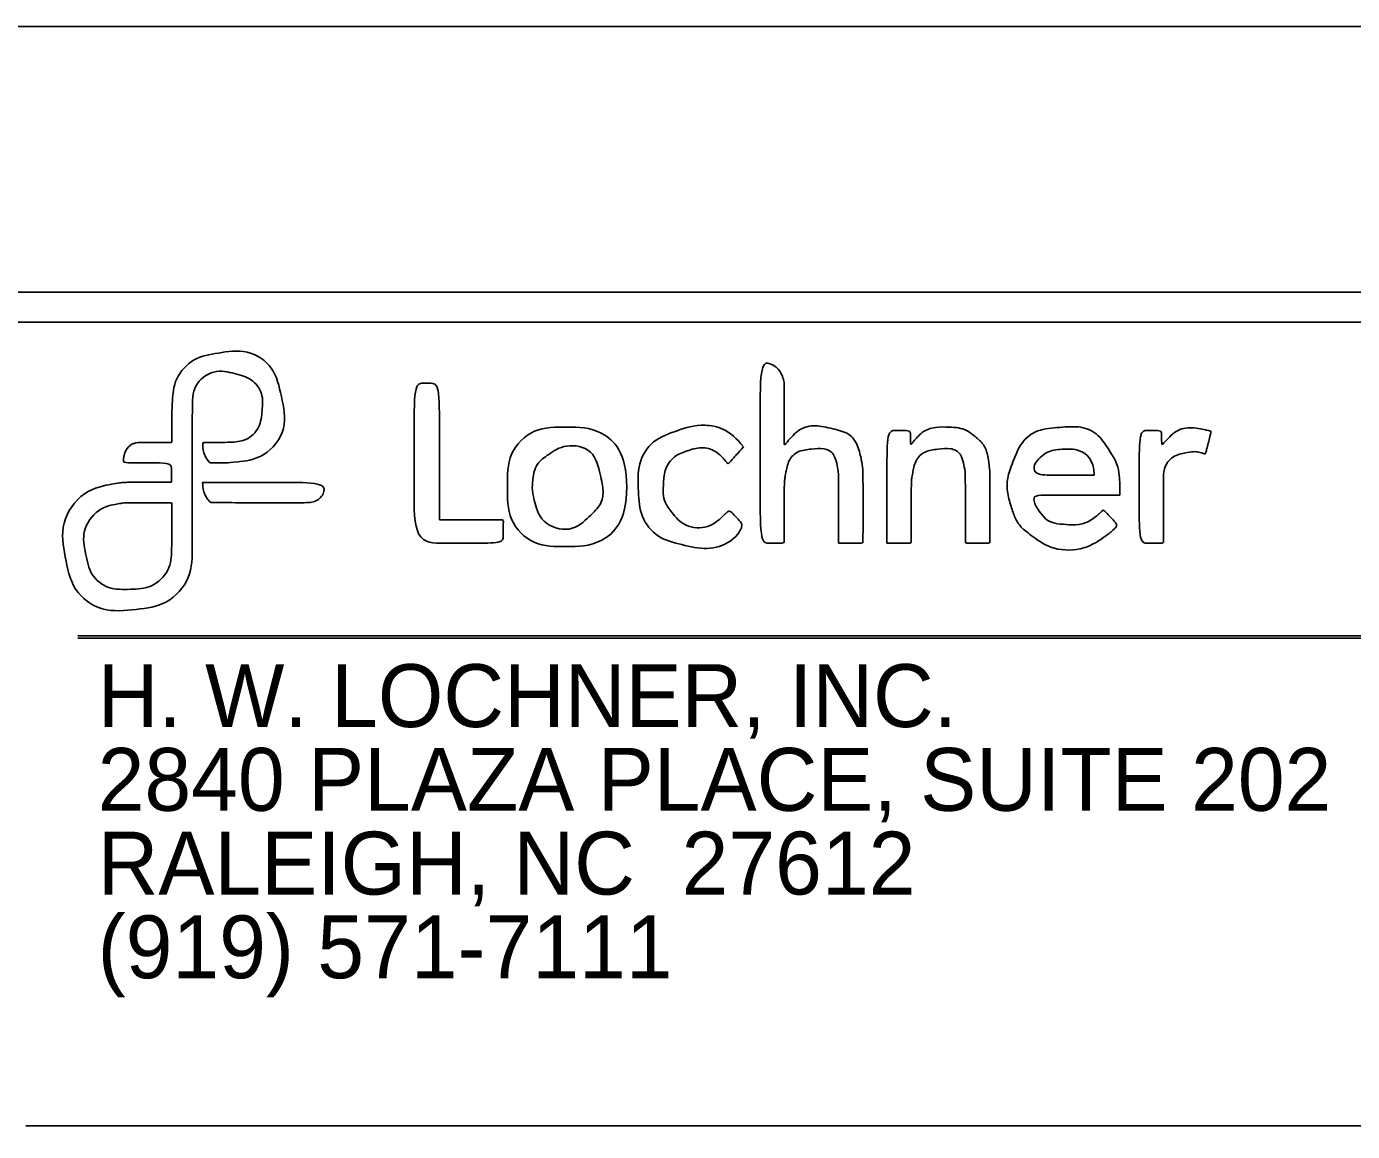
# Model space of a CAD drawing. Extents: x 2044835 to 2046519, y 755505 to 756605.
# Drawn here: x 2046101.6 to 2046213.7, y 756512 to 756605.4 of the extents above; entities that cross this region are included whole.
import ezdxf

# ---------------------------------------------------------------- set-up
doc = ezdxf.new("R2010")
doc.units = 0
for name, color, linetype in [('Default', 7, 'Continuous'), ('Old_Level_1', 7, 'Continuous'), ('Old_Level_4', 7, 'Continuous'), ('Sheet Cutting Line CELL', 7, 'Continuous'), ('Sheet Plot Border Inside CELL', 7, 'Continuous'), ('Sheet Plot Border Outside CELL', 7, 'Continuous'), ('Sheet Profile CELL', 7, 'Continuous'), ('Sheet Profile Grid Middle CELL', 7, 'Continuous'), ('Sheet Profile Grid Minor CELL', 7, 'Continuous')]:
    doc.layers.add(name, color=color, linetype=linetype)

msp = doc.modelspace()

# ---------------------------------------------------------------- linework, layer by layer
at = {"layer": 'Default'}
for points in [[(2046113.9, 756566.88), (2046113.78, 756566.88), (2046113.69, 756566.88), (2046113.59, 756566.88), (2046112.51, 756566.88), (2046111.42, 756566.89), (2046110.34, 756566.88), (2046109.97, 756566.87), (2046109.59, 756566.84), (2046109.23, 756566.78), (2046106.39, 756566.29), (2046104.39, 756563.42), (2046104.91, 756560.59), (2046105.45, 756557.68), (2046107.99, 756555.81), (2046110.95, 756556.14), (2046113.55, 756556.43), (2046115.65, 756558.77), (2046115.65, 756561.39), (2046115.65, 756565.32), (2046115.65, 756569.25), (2046115.65, 756573.18), (2046115.66, 756575.1), (2046117.45, 756576.51), (2046119.3, 756576.05), (2046120.7, 756575.7), (2046121.68, 756574.37), (2046121.55, 756572.96), (2046121.42, 756571.48), (2046120.23, 756570.32), (2046118.74, 756570.26), (2046118.1, 756570.23), (2046117.46, 756570.25), (2046116.82, 756570.24), (2046116.72, 756570.24), (2046116.62, 756570.23), (2046116.5, 756570.22), (2046116.56, 756569.62), (2046116.7, 756569.09), (2046117.04, 756568.62), (2046117.08, 756568.56), (2046117.19, 756568.52), (2046117.26, 756568.52), (2046117.89, 756568.53), (2046118.53, 756568.5), (2046119.15, 756568.57), (2046121.79, 756568.84), (2046123.78, 756571.38), (2046123.17, 756574.18), (2046122.62, 756576.68), (2046120.32, 756578.2), (2046117.76, 756577.79), (2046115.76, 756577.47), (2046114.08, 756575.66), (2046113.96, 756573.64), (2046113.9, 756572.62), (2046113.93, 756571.6), (2046113.92, 756570.58), (2046113.92, 756570.48), (2046113.92, 756570.38), (2046113.92, 756570.24), (2046113.79, 756570.24), (2046113.7, 756570.24), (2046113.61, 756570.24), (2046112.89, 756570.24), (2046112.17, 756570.25), (2046111.45, 756570.24), (2046110.69, 756570.24), (2046110.06, 756569.77), (2046109.87, 756569.05), (2046109.83, 756568.88), (2046109.83, 756568.7), (2046109.8, 756568.51), (2046111.21, 756568.51), (2046112.55, 756568.51), (2046113.9, 756568.51), (2046113.9, 756567.96), (2046113.9, 756567.44), (2046113.9, 756566.88)], [(2046170.27, 756561.72), (2046170.98, 756561.72), (2046171.65, 756561.72), (2046172.34, 756561.72), (2046172.34, 756561.79), (2046172.34, 756561.85), (2046172.34, 756561.91), (2046172.35, 756563.75), (2046172.35, 756565.6), (2046172.34, 756567.44), (2046172.34, 756567.83), (2046172.31, 756568.22), (2046172.23, 756568.6), (2046171.96, 756570), (2046171.24, 756571.05), (2046169.79, 756571.4), (2046168.28, 756571.77), (2046166.94, 756571.45), (2046165.89, 756570.23), (2046165.84, 756570.17), (2046165.79, 756570.12), (2046165.69, 756570.01), (2046165.69, 756570.19), (2046165.69, 756570.28), (2046165.69, 756570.37), (2046165.69, 756571.95), (2046165.69, 756573.52), (2046165.68, 756575.1), (2046165.68, 756575.31), (2046165.64, 756575.53), (2046165.57, 756575.73), (2046165.29, 756576.48), (2046164.35, 756577.04), (2046163.64, 756576.88), (2046163.64, 756571.83), (2046163.64, 756566.78), (2046163.64, 756561.73), (2046164.33, 756561.73), (2046165, 756561.73), (2046165.69, 756561.73), (2046165.69, 756561.85), (2046165.69, 756561.95), (2046165.69, 756562.06), (2046165.69, 756563.53), (2046165.68, 756565), (2046165.69, 756566.47), (2046165.7, 756566.84), (2046165.73, 756567.22), (2046165.8, 756567.58), (2046166.02, 756568.78), (2046166.8, 756569.55), (2046167.96, 756569.68), (2046169.09, 756569.81), (2046169.96, 756569.33), (2046170.19, 756568.13), (2046170.24, 756567.87), (2046170.27, 756567.6), (2046170.27, 756567.33), (2046170.28, 756566.21), (2046170.27, 756565.08), (2046170.27, 756563.96), (2046170.27, 756563.22), (2046170.27, 756562.48), (2046170.27, 756561.72)], [(2046136.54, 756563.7), (2046136.54, 756567.57), (2046136.54, 756571.41), (2046136.54, 756575.25), (2046135.81, 756575.25), (2046135.11, 756575.25), (2046134.39, 756575.25), (2046134.39, 756570.74), (2046134.39, 756566.23), (2046134.39, 756561.72), (2046136.91, 756561.72), (2046139.41, 756561.72), (2046141.93, 756561.72), (2046141.93, 756562.3), (2046141.92, 756562.86), (2046141.94, 756563.42), (2046141.95, 756563.65), (2046141.88, 756563.71), (2046141.65, 756563.71), (2046140.06, 756563.7), (2046138.48, 756563.7), (2046136.89, 756563.7), (2046136.79, 756563.7), (2046136.69, 756563.7), (2046136.54, 756563.7)], [(2046152.37, 756566.49), (2046152.38, 756569.36), (2046150.2, 756571.55), (2046147.34, 756571.55), (2046144.47, 756571.55), (2046142.28, 756569.37), (2046142.28, 756566.51), (2046142.28, 756563.63), (2046144.45, 756561.44), (2046147.28, 756561.44), (2046150.2, 756561.44), (2046152.37, 756563.59), (2046152.37, 756566.49)], [(2046162.23, 756569.86), (2046161.14, 756571.36), (2046158.75, 756571.97), (2046156.64, 756571.24), (2046154.5, 756570.49), (2046153.24, 756568.5), (2046153.36, 756566.06), (2046153.47, 756563.92), (2046154.95, 756562.11), (2046157.02, 756561.61), (2046159.16, 756561.09), (2046161.25, 756561.73), (2046162.31, 756563.2), (2046161.89, 756563.65), (2046161.46, 756564.1), (2046161.07, 756564.51), (2046160.9, 756564.37), (2046160.74, 756564.25), (2046160.6, 756564.11), (2046159.36, 756562.92), (2046157.2, 756563.05), (2046156.14, 756564.4), (2046155.58, 756565.11), (2046155.42, 756565.93), (2046155.48, 756566.82), (2046155.55, 756568.04), (2046156.36, 756569.14), (2046157.47, 756569.52), (2046158.65, 756569.93), (2046159.95, 756569.57), (2046160.77, 756568.62), (2046160.82, 756568.57), (2046160.86, 756568.51), (2046160.94, 756568.4), (2046161.38, 756568.91), (2046161.8, 756569.37), (2046162.23, 756569.86)], [(2046174.37, 756561.72), (2046175.06, 756561.72), (2046175.73, 756561.72), (2046176.42, 756561.72), (2046176.42, 756561.85), (2046176.42, 756561.95), (2046176.42, 756562.05), (2046176.42, 756563.56), (2046176.42, 756565.06), (2046176.43, 756566.57), (2046176.43, 756566.9), (2046176.46, 756567.23), (2046176.52, 756567.55), (2046176.74, 756568.76), (2046177.53, 756569.54), (2046178.68, 756569.68), (2046179.77, 756569.81), (2046180.66, 756569.37), (2046180.91, 756568.16), (2046180.96, 756567.92), (2046180.99, 756567.67), (2046180.99, 756567.42), (2046181, 756565.62), (2046181, 756563.82), (2046181, 756562.02), (2046181, 756561.92), (2046181, 756561.82), (2046181, 756561.72), (2046181.71, 756561.72), (2046182.38, 756561.72), (2046183.07, 756561.72), (2046183.07, 756561.84), (2046183.07, 756561.93), (2046183.07, 756562.02), (2046183.07, 756563.72), (2046183.07, 756565.42), (2046183.07, 756567.11), (2046183.07, 756567.49), (2046183.06, 756567.88), (2046183.01, 756568.25), (2046182.9, 756569.28), (2046182.53, 756570.18), (2046181.7, 756570.84), (2046181.11, 756571.3), (2046180.43, 756571.5), (2046179.69, 756571.53), (2046178.43, 756571.59), (2046177.34, 756571.21), (2046176.52, 756570.2), (2046176.48, 756570.16), (2046176.44, 756570.12), (2046176.36, 756570.03), (2046176.36, 756570.48), (2046176.36, 756570.86), (2046176.36, 756571.25), (2046175.68, 756571.25), (2046175.03, 756571.25), (2046174.37, 756571.25), (2046174.37, 756568.07), (2046174.37, 756564.91), (2046174.37, 756561.72)], [(2046194.05, 756565.79), (2046194.05, 756566.14), (2046194.07, 756566.46), (2046194.05, 756566.78), (2046194, 756567.72), (2046193.77, 756568.61), (2046193.27, 756569.41), (2046192.28, 756570.98), (2046190.82, 756571.66), (2046188.99, 756571.52), (2046187.02, 756571.37), (2046185.68, 756570.32), (2046184.98, 756568.5), (2046184.5, 756567.24), (2046184.51, 756565.94), (2046184.92, 756564.66), (2046185.22, 756563.73), (2046185.76, 756562.98), (2046186.55, 756562.4), (2046188.34, 756561.08), (2046191.17, 756561.11), (2046193.02, 756562.46), (2046193.33, 756562.69), (2046193.6, 756562.96), (2046193.91, 756563.23), (2046193.48, 756563.7), (2046193.08, 756564.12), (2046192.68, 756564.55), (2046192.6, 756564.48), (2046192.53, 756564.42), (2046192.46, 756564.35), (2046191.6, 756563.6), (2046190.61, 756563.24), (2046189.47, 756563.31), (2046188.54, 756563.37), (2046187.74, 756563.71), (2046187.19, 756564.51), (2046186.93, 756564.88), (2046186.78, 756565.3), (2046186.76, 756565.79), (2046187.99, 756565.79), (2046189.2, 756565.79), (2046190.4, 756565.79), (2046191.61, 756565.79), (2046192.82, 756565.79), (2046194.05, 756565.79)], [(2046201.76, 756571.1), (2046201.76, 756571.14), (2046201.76, 756571.17), (2046201.76, 756571.21), (2046201.72, 756571.21), (2046201.68, 756571.21), (2046201.64, 756571.22), (2046200.12, 756571.59), (2046198.78, 756571.33), (2046197.71, 756570.12), (2046197.7, 756570.1), (2046197.66, 756570.09), (2046197.59, 756570.06), (2046197.59, 756570.48), (2046197.59, 756570.86), (2046197.59, 756571.25), (2046196.94, 756571.25), (2046196.32, 756571.25), (2046195.69, 756571.25), (2046195.69, 756568.06), (2046195.69, 756564.89), (2046195.69, 756561.72), (2046196.37, 756561.72), (2046197.04, 756561.72), (2046197.74, 756561.72), (2046197.74, 756561.83), (2046197.74, 756561.93), (2046197.74, 756562.03), (2046197.74, 756563.66), (2046197.73, 756565.29), (2046197.74, 756566.91), (2046197.74, 756568.23), (2046198.59, 756569.2), (2046199.89, 756569.41), (2046200.36, 756569.49), (2046200.82, 756569.42), (2046201.28, 756569.24), (2046201.3, 756569.34), (2046201.33, 756569.42), (2046201.35, 756569.5), (2046201.49, 756570.03), (2046201.63, 756570.57), (2046201.76, 756571.1)], [(2046144.39, 756566.36), (2046144.42, 756567.58), (2046144.76, 756568.53), (2046145.69, 756569.18), (2046147.13, 756570.18), (2046149.62, 756569.76), (2046150.17, 756567.37), (2046150.45, 756566.13), (2046150.24, 756564.97), (2046149.29, 756564.06), (2046147.68, 756562.53), (2046145.03, 756563.37), (2046144.51, 756565.56), (2046144.44, 756565.87), (2046144.41, 756566.18), (2046144.39, 756566.36)], [(2046191.89, 756567.48), (2046190.19, 756567.48), (2046188.5, 756567.48), (2046186.8, 756567.48), (2046186.69, 756568.42), (2046187.89, 756569.57), (2046189.08, 756569.66), (2046190.65, 756569.77), (2046191.85, 756568.84), (2046191.89, 756567.48)], [(2046116.51, 756566.87), (2046116.56, 756566.28), (2046116.71, 756565.74), (2046117.07, 756565.29), (2046117.12, 756565.21), (2046117.25, 756565.16), (2046117.35, 756565.16), (2046119.96, 756565.15), (2046122.57, 756565.14), (2046125.18, 756565.15), (2046126.13, 756565.16), (2046126.9, 756566.01), (2046126.76, 756566.87), (2046123.36, 756566.87), (2046119.95, 756566.87), (2046116.51, 756566.87)], [(2046113.9, 756565.14), (2046113.8, 756565.14), (2046113.73, 756565.15), (2046113.67, 756565.15), (2046112.51, 756565.15), (2046111.36, 756565.15), (2046110.21, 756565.15), (2046109.98, 756565.15), (2046109.76, 756565.12), (2046109.53, 756565.08), (2046107.62, 756564.75), (2046106.25, 756562.75), (2046106.63, 756560.86), (2046107, 756558.98), (2046108.52, 756557.78), (2046110.43, 756557.83), (2046112.23, 756557.88), (2046113.84, 756559.41), (2046113.9, 756561.2), (2046113.94, 756562.46), (2046113.92, 756563.73), (2046113.92, 756564.99), (2046113.92, 756565.03), (2046113.91, 756565.08), (2046113.9, 756565.14)], [(2046113.9, 756565.14), (2046113.91, 756565.08), (2046113.92, 756565.03), (2046113.92, 756564.99), (2046113.92, 756563.73), (2046113.94, 756562.46), (2046113.9, 756561.2), (2046113.84, 756559.41), (2046112.23, 756557.88), (2046110.43, 756557.83), (2046108.52, 756557.78), (2046107, 756558.98), (2046106.63, 756560.86), (2046106.25, 756562.75), (2046107.62, 756564.75), (2046109.53, 756565.08), (2046109.76, 756565.12), (2046109.98, 756565.15), (2046110.21, 756565.15), (2046111.36, 756565.15), (2046112.51, 756565.15), (2046113.67, 756565.15), (2046113.73, 756565.15), (2046113.8, 756565.14), (2046113.9, 756565.14)], [(2046113.9, 756565.14), (2046113.91, 756565.08), (2046113.92, 756565.03), (2046113.92, 756564.99), (2046113.92, 756563.73), (2046113.94, 756562.46), (2046113.9, 756561.2), (2046113.84, 756559.41), (2046112.23, 756557.88), (2046110.43, 756557.83), (2046108.52, 756557.78), (2046107, 756558.98), (2046106.63, 756560.86), (2046106.25, 756562.75), (2046107.62, 756564.75), (2046109.53, 756565.08), (2046109.76, 756565.12), (2046109.98, 756565.15), (2046110.21, 756565.15), (2046111.36, 756565.15), (2046112.51, 756565.15), (2046113.67, 756565.15), (2046113.73, 756565.15), (2046113.8, 756565.14), (2046113.9, 756565.14)]]:
    msp.add_open_spline(points, degree=3, dxfattribs=at)
at = {"layer": 'Old_Level_1'}
for p, q in [((2046105.97, 756553.9), (2046291.73, 756553.9)), ((2046105.97, 756553.71), (2046291.73, 756553.71))]:
    msp.add_line(p, q, dxfattribs=at)
at = {"layer": 'Old_Level_4'}
msp.add_line((2046101.58, 756512.46), (2046301.63, 756512.46), dxfattribs=at)
at = {"layer": 'Sheet Cutting Line CELL'}
msp.add_line((2046518.63, 756605.41), (2044834.63, 756605.41), dxfattribs=at)
at = {"layer": 'Sheet Plot Border Inside CELL'}
msp.add_lwpolyline([(2044847.63, 755527.86), (2046514.13, 755527.86), (2046514.13, 756582.96), (2044847.63, 756582.96)], close=True, dxfattribs=at)
at = {"layer": 'Sheet Plot Border Outside CELL'}
msp.add_lwpolyline([(2044834.63, 755505.41), (2046518.63, 755505.41), (2046518.63, 756605.41), (2044834.63, 756605.41)], close=True, dxfattribs=at)
at = {"layer": 'Sheet Profile CELL'}
msp.add_lwpolyline([(2046501.63, 756580.41), (2045001.63, 756580.41), (2045001.63, 755530.41), (2046501.63, 755530.41)], close=True, dxfattribs=at)
at = {"layer": 'Sheet Profile Grid Middle CELL'}
msp.add_line((2046126.63, 756580.41), (2046176.63, 756580.41), dxfattribs=at)
at = {"layer": 'Sheet Profile Grid Minor CELL'}
for p, q in [((2046096.63, 756580.41), (2046106.63, 756580.41)), ((2046111.63, 756580.41), (2046116.63, 756580.41)), ((2046121.63, 756580.41), (2046131.63, 756580.41)), ((2046136.63, 756580.41), (2046141.63, 756580.41)), ((2046146.63, 756580.41), (2046156.63, 756580.41)), ((2046161.63, 756580.41), (2046166.63, 756580.41)), ((2046171.63, 756580.41), (2046181.63, 756580.41)), ((2046186.63, 756580.41), (2046191.63, 756580.41))]:
    msp.add_line(p, q, dxfattribs=at)

# ---------------------------------------------------------------- texts
at = {"layer": 'Old_Level_1'}
for s, p in [('H. W. LOCHNER, INC.', (2046107.65, 756546.18)), ('H. W. LOCHNER, INC.', (2046107.65, 756546.18)), ('2840 PLAZA PLACE, SUITE 202', (2046107.65, 756539.1)), ('2840 PLAZA PLACE, SUITE 202', (2046107.65, 756539.1)), ('RALEIGH, NC  27612', (2046107.65, 756532.02)), ('(919) 571-7111', (2046107.65, 756524.94))]:
    msp.add_text(s, height=5.3144, rotation=360, dxfattribs=at).set_placement(p)

doc.saveas('drawing.dxf')
